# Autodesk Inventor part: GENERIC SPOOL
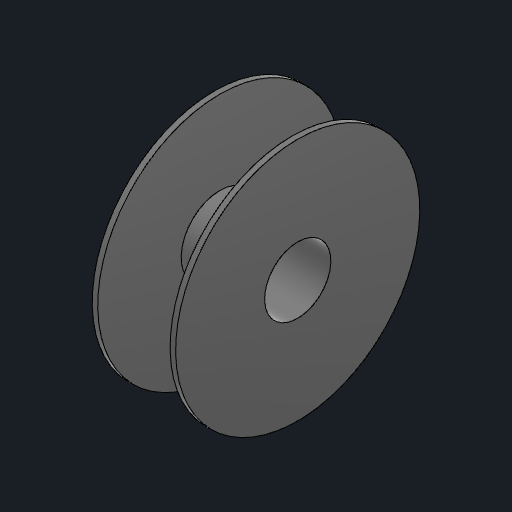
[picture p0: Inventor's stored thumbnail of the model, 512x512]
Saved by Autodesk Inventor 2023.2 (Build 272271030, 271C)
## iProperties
Created: 2023-04
Part Number: GENERIC SPOOL
Material: Generic
Document SubType Name: Modeling
Designer: AR
Mass: 308.105 g
Surface Area: 1424.35 cm^2
Volume: 308.105 cm^3
Density: 1 g/cm^3
Appearance: Default
Author: AR
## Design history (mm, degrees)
derived "_2 SPOOL CORD WRAP MP.ipt"
feature "GENERIC SPOOL::_2 SPOOL CORD WRAP MP.ipt" dims "d0" = 10
tag "TaggingFeature1"
node "GENERIC SPOOL"
